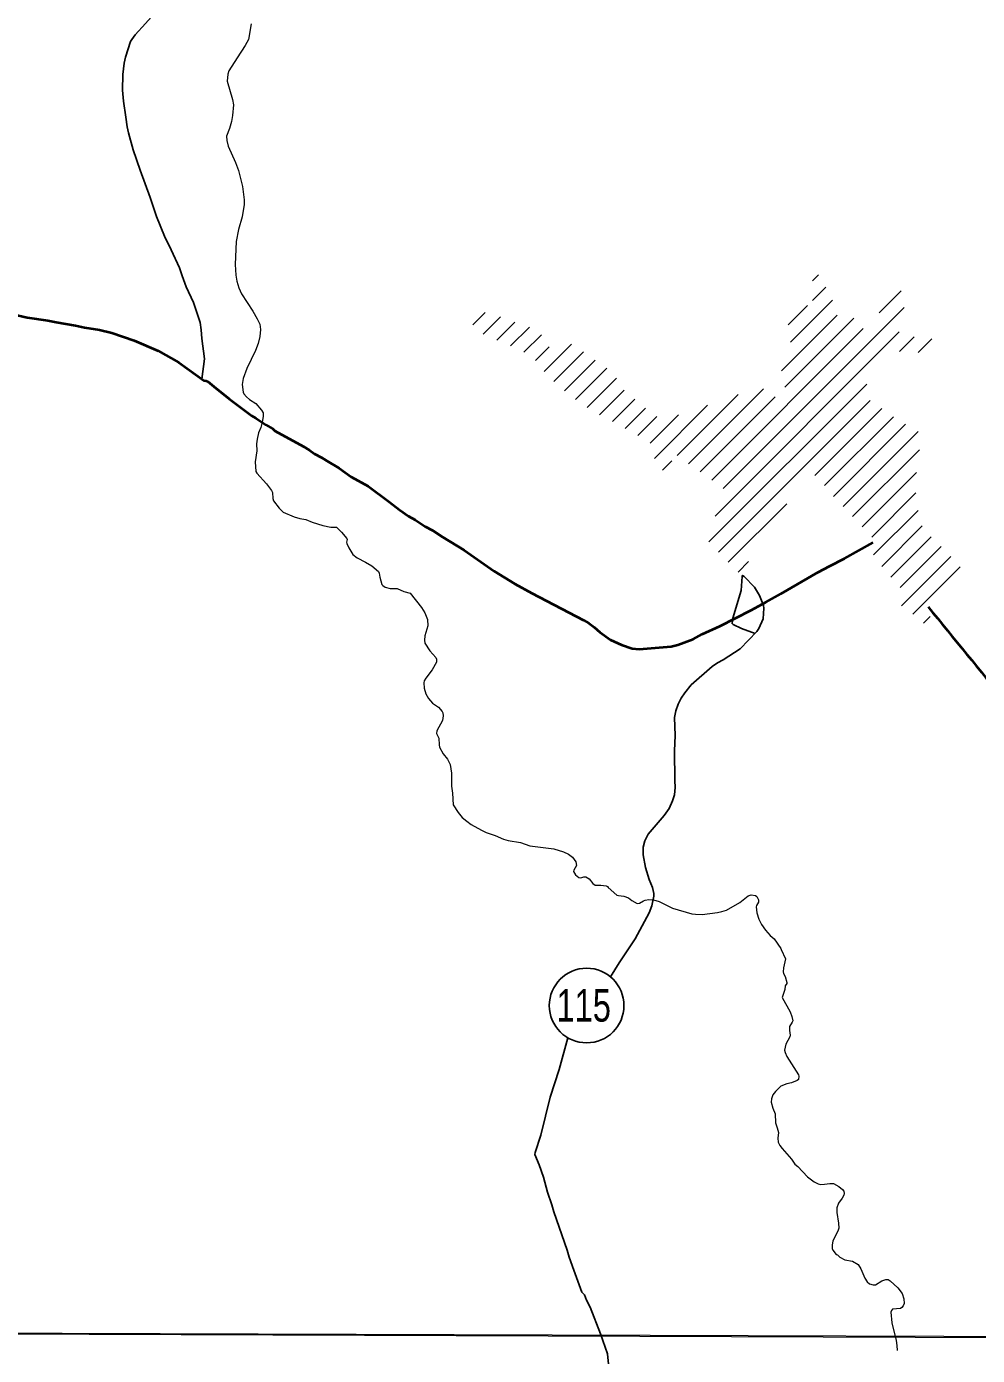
# Model space of a CAD drawing. Extents: x 553962 to 842807, y 8883888 to 9032388.
# Drawn here: x 614032 to 616078, y 8909821 to 8912681 of the extents above; entities that cross this region are included whole.
import ezdxf
from ezdxf.enums import TextEntityAlignment as Align

# ---------------------------------------------------------------- set-up
doc = ezdxf.new("R2010")
doc.units = 0
doc.header["$LTSCALE"] = 150
doc.layers.add('6', color=7, linetype='Continuous', lineweight=13)

msp = doc.modelspace()

# ---------------------------------------------------------------- linework, layer by layer
at = {"layer": '6'}
for p, q in [((615722.8, 8912133.8), (615735.8, 8912146.7)), ((615723.1, 8912091.6), (615751.6, 8912120.1)), ((615866.2, 8912064.9), (615913.5, 8912112.3)), ((615675.8, 8912001.9), (615765.9, 8912092)), ((614991.9, 8912039.2), (615018.6, 8912065.9)), ((615014.2, 8912019), (615051.5, 8912056.4)), ((615530.8, 8911687.2), (615920.2, 8912076.6)), ((615656.6, 8911940.3), (615776.4, 8912060.1)), ((615663.6, 8911904.8), (615812.3, 8912053.5)), ((615670.7, 8912039.2), (615712.3, 8912080.8)), ((615043.8, 8912006.3), (615082.5, 8912044.9)), ((615073.5, 8911993.6), (615114.1, 8912034.1)), ((615506.2, 8911705), (615832.4, 8912031.2)), ((615102.3, 8911979.9), (615140.1, 8912017.8)), ((615145.9, 8911938.7), (615204.6, 8911997.4)), ((615513.3, 8911627.3), (615909.8, 8912023.7)), ((615910.3, 8911981.8), (615942, 8912013.5)), ((615950.2, 8911979.3), (615979.5, 8912008.6)), ((615127, 8911962.2), (615156.3, 8911991.4)), ((615166.7, 8911917), (615230.7, 8911981)), ((615189.2, 8911897.1), (615255.5, 8911963.4)), ((615213, 8911878.5), (615280.3, 8911945.8)), ((615238.2, 8911861.3), (615301.4, 8911924.5)), ((615500.3, 8911571.8), (615839.7, 8911911.2)), ((615265.1, 8911845.7), (615317.8, 8911898.4)), ((615431.6, 8911757.6), (615562.9, 8911888.9)), ((615456.2, 8911739.8), (615617.5, 8911901.2)), ((615481.7, 8911722.9), (615642.7, 8911883.9)), ((615292.7, 8911830.9), (615340.7, 8911878.9)), ((615320.2, 8911816), (615363.8, 8911859.6)), ((615382.8, 8911751.2), (615497.4, 8911865.9)), ((615521.1, 8911550.2), (615847.5, 8911876.6)), ((615728.4, 8911715.1), (615872.1, 8911858.8)), ((615347.4, 8911800.8), (615388.4, 8911841.7)), ((615373.7, 8911784.6), (615434.8, 8911845.7)), ((615748.9, 8911693.2), (615897, 8911841.2)), ((615768.1, 8911669.9), (615923.5, 8911825.3)), ((615788.8, 8911648.1), (615950.1, 8911809.5)), ((615809.4, 8911626.3), (615953.2, 8911770.2)), ((615400.2, 8911726.3), (615420.1, 8911746.2)), ((615830, 8911604.6), (615946.5, 8911721.1)), ((615541.9, 8911528.6), (615667.5, 8911654.2)), ((615850.5, 8911582.5), (615945.5, 8911677.5)), ((615854.5, 8911544.2), (615950.1, 8911639.7)), ((615872.1, 8911519.3), (615959.2, 8911606.5)), ((615891.5, 8911496.3), (615978.4, 8911583.2)), ((615911.6, 8911474), (616000, 8911562.4)), ((615914.5, 8911434.4), (616020.8, 8911540.8)), ((615562.9, 8911507.2), (615585.5, 8911529.7)), ((615938.9, 8911416.4), (616040.5, 8911518)), ((615961.7, 8911396.8), (615976.5, 8911411.6)), ((574653.9, 8910009.3), (626625.7, 8909822.1))]:
    msp.add_line(p, q, dxfattribs=at)
at = {"layer": '6', "lineweight": 25}
msp.add_line((615138.8, 8910295.4), (615126.6, 8910258.3), dxfattribs=at)
for points in [[(614353.8, 8912761.2), (614336.9, 8912742.6), (614312.7, 8912712.9), (614299.8, 8912700.8), (614288.1, 8912687.2), (614265.4, 8912663), (614258.3, 8912653.2), (614256, 8912648.7), (614244.8, 8912614.9), (614242.1, 8912602.1), (614238.8, 8912578), (614238.7, 8912544.3), (614240.6, 8912520.4), (614245.5, 8912486.2)], [(614245.5, 8912486.2), (614248.5, 8912465.4), (614251.4, 8912452.5), (614261.7, 8912415.4), (614276.3, 8912371.6), (614298, 8912313.3), (614311.5, 8912271.9), (614311.5, 8912271.9), (614328.6, 8912229.8), (614343.1, 8912200.7), (614360.8, 8912161.7), (614367, 8912144.3)], [(614367, 8912144.3), (614375.3, 8912120.7), (614391.5, 8912087.1), (614405.8, 8912044.1), (614407.9, 8912028.6), (614409.2, 8912009.7), (614415.2, 8911965.8), (614409.2, 8911922.5)], [(615599.9, 8911375), (615570.6, 8911385.8), (615552.6, 8911394.1), (615550.1, 8911396.3), (615552, 8911408.1), (615569.5, 8911467.6), (615571.8, 8911497.7), (615572.6, 8911500), (615576.1, 8911497.3), (615598, 8911474.4), (615609.3, 8911456.9), (615617.4, 8911434.8), (615618, 8911429.4), (615616.8, 8911406.4), (615607.9, 8911385.5), (615603.3, 8911379.1), (615567.2, 8911342.2), (615530.8, 8911318.5), (615518.9, 8911311.9), (615507.1, 8911303.9), (615461.7, 8911264.1), (615448.1, 8911247.4), (615440.7, 8911235.9), (615434.2, 8911222.9), (615429.1, 8911208.4), (615426.1, 8911193.8), (615427.6, 8911155.1), (615426.4, 8911122.4), (615426.8, 8911058.8), (615427.6, 8911043.4), (615425.9, 8911028), (615422.1, 8911015), (615414.6, 8910998.4), (615403.9, 8910983.4), (615369.6, 8910943.1), (615362.5, 8910929), (615358.7, 8910915.2), (615358.7, 8910898.9), (615363.5, 8910871.4), (615371.8, 8910845.5), (615378.5, 8910828.5), (615382, 8910815.5), (615381.8, 8910809.8), (615377.1, 8910788.9), (615371.3, 8910773.5), (615341.2, 8910717.8), (615307.1, 8910666.5), (615288.4, 8910636.1)], [(615196.8, 8910504.9), (615177.9, 8910436.4), (615158.9, 8910377.1), (615138.8, 8910295.4)], [(615126.6, 8910258.3), (615125.9, 8910253.6), (615134.7, 8910231.8), (615144, 8910204.7), (615152.8, 8910172.4), (615162.3, 8910145.7), (615166.8, 8910130.4), (615195.1, 8910047.8), (615199.5, 8910032.8), (615209.6, 8910005.2)], [(615209.6, 8910005.2), (615227, 8909957.6), (615232.7, 8909951.5), (615237, 8909940.3), (615244.4, 8909924.9), (615267.1, 8909868.1), (615282, 8909824.9)], [(615282, 8909824.9), (615292.5, 8909716.1), (615320.5, 8909565.2), (615327.5, 8909531.6), (615344.7, 8909497.9), (615365.9, 8909445.9), (615390.2, 8909408.2), (615414.6, 8909376.6), (615454.1, 8909327.6), (615483.5, 8909293.9), (615556.6, 8909207.2), (615624.7, 8909143.6), (615643.3, 8909127.9), (615658.6, 8909118.9)]]:
    msp.add_lwpolyline(points, dxfattribs=at)
at = {"layer": '6'}
for points in [[(614515.1, 8912686.6), (614509.3, 8912653.2), (614502.2, 8912639.9), (614484.8, 8912613.7), (614467.5, 8912585.5), (614465.3, 8912578.2), (614464, 8912563.3), (614475.1, 8912524.1), (614477.1, 8912512.2), (614475.3, 8912489.2), (614472.9, 8912476.4), (614468.8, 8912461.3), (614462.4, 8912445.2), (614462.6, 8912435.7), (614465.5, 8912423.8), (614481.8, 8912388.7), (614488.3, 8912371.2), (614496.7, 8912337), (614500.2, 8912308.2), (614500.5, 8912297.9), (614495.6, 8912271.6), (614487.7, 8912244.4), (614483.1, 8912218.1), (614480.7, 8912168.7), (614482.5, 8912145.7), (614484.5, 8912132.9)], [(614515.1, 8912686.6), (614509.3, 8912653.2), (614502.2, 8912639.9), (614484.8, 8912613.7), (614467.5, 8912585.5), (614465.3, 8912578.2), (614464, 8912563.3), (614475.1, 8912524.1), (614477.1, 8912512.2), (614475.3, 8912489.2), (614472.9, 8912476.4), (614468.8, 8912461.3), (614462.4, 8912445.2), (614462.6, 8912435.7), (614465.5, 8912423.8), (614481.8, 8912388.7), (614488.3, 8912371.2), (614496.7, 8912337), (614500.2, 8912308.2), (614500.5, 8912297.9), (614495.6, 8912271.6), (614487.7, 8912244.4), (614483.1, 8912218.1), (614480.7, 8912168.7), (614482.5, 8912145.7), (614484.5, 8912132.9)], [(614484.5, 8912132.9), (614488.5, 8912118.5), (614494.8, 8912105.6), (614519, 8912068.7), (614528.5, 8912052.3), (614533.6, 8912040.3), (614535.2, 8912029.2), (614534.1, 8912013.9), (614530.5, 8911998.8), (614524.3, 8911983.7), (614505.6, 8911945.2), (614498.3, 8911923.7), (614495.8, 8911911), (614498.1, 8911894.5), (614499.6, 8911890.4), (614505.2, 8911884.2), (614511.7, 8911878.7), (614525.4, 8911869.5), (614537.6, 8911855.5), (614541.2, 8911849.9), (614540.9, 8911842.1), (614539, 8911829.5), (614535.8, 8911818.4), (614530.9, 8911806.4), (614528.1, 8911793), (614527.1, 8911782.7), (614527.6, 8911768.3), (614524, 8911744.5), (614525, 8911723.2), (614527.2, 8911719.7), (614548.6, 8911697.1), (614559.2, 8911682.3), (614561, 8911678.1), (614562.1, 8911665.3), (614563.3, 8911660.1), (614575.8, 8911644.3), (614584.1, 8911636.2)], [(614484.5, 8912132.9), (614488.5, 8912118.5), (614494.8, 8912105.6), (614519, 8912068.7), (614528.5, 8912052.3), (614533.6, 8912040.3), (614535.2, 8912029.2), (614534.1, 8912013.9), (614530.5, 8911998.8), (614524.3, 8911983.7), (614505.6, 8911945.2), (614498.3, 8911923.7), (614495.8, 8911911), (614498.1, 8911894.5), (614499.6, 8911890.4), (614505.2, 8911884.2), (614511.7, 8911878.7), (614525.4, 8911869.5), (614537.6, 8911855.5), (614541.2, 8911849.9), (614540.9, 8911842.1), (614539, 8911829.5), (614535.8, 8911818.4), (614530.9, 8911806.4), (614528.1, 8911793), (614527.1, 8911782.7), (614527.6, 8911768.3), (614524, 8911744.5), (614525, 8911723.2), (614527.2, 8911719.7), (614548.6, 8911697.1), (614559.2, 8911682.3), (614561, 8911678.1), (614562.1, 8911665.3), (614563.3, 8911660.1), (614575.8, 8911644.3), (614584.1, 8911636.2)], [(614584.1, 8911636.2), (614584.1, 8911636.2), (614608.1, 8911626), (614620.1, 8911622.5), (614632.8, 8911620.1), (614646.4, 8911614.5), (614669.5, 8911607.6), (614686.7, 8911603.6), (614699.1, 8911603.5)], [(614584.1, 8911636.2), (614584.1, 8911636.2), (614608.1, 8911626), (614620.1, 8911622.5), (614632.8, 8911620.1), (614646.4, 8911614.5), (614669.5, 8911607.6), (614686.7, 8911603.6), (614699.1, 8911603.5)], [(614699.1, 8911603.5), (614709.6, 8911592.7), (614721, 8911579.5), (614721.7, 8911577.4), (614720.5, 8911571.3), (614720.9, 8911568.5), (614725.2, 8911559.5), (614733.7, 8911545.2), (614743, 8911537.5), (614761.4, 8911528.7), (614774.6, 8911520.4), (614789, 8911508.1), (614790.7, 8911504.8), (614791.9, 8911496.1), (614796.7, 8911480.4), (614798.5, 8911478), (614803.8, 8911474.7), (614814.1, 8911471.6), (614829.7, 8911471.7), (614843.8, 8911465.2), (614857.7, 8911461.5)], [(614699.1, 8911603.5), (614709.6, 8911592.7), (614721, 8911579.5), (614721.7, 8911577.4), (614720.5, 8911571.3), (614720.9, 8911568.5), (614725.2, 8911559.5), (614733.7, 8911545.2), (614743, 8911537.5), (614761.4, 8911528.7), (614774.6, 8911520.4), (614789, 8911508.1), (614790.7, 8911504.8), (614791.9, 8911496.1), (614796.7, 8911480.4), (614798.5, 8911478), (614803.8, 8911474.7), (614814.1, 8911471.6), (614829.7, 8911471.7), (614843.8, 8911465.2), (614857.7, 8911461.5)], [(614857.7, 8911461.5), (614881.8, 8911430.8), (614888.6, 8911419.2), (614894.8, 8911405.2)], [(614857.7, 8911461.5), (614881.8, 8911430.8), (614888.6, 8911419.2), (614894.8, 8911405.2)], [(614894.8, 8911405.2), (614895.4, 8911391.4), (614888.9, 8911370.2), (614888.4, 8911360.8), (614889.1, 8911353.8), (614899.5, 8911337.6), (614912.4, 8911323), (614913.7, 8911319.3), (614914.2, 8911313.3), (614904.9, 8911296.6), (614891.1, 8911278.7), (614887.5, 8911272.7), (614886.7, 8911268.4), (614887.5, 8911257.1), (614891.3, 8911245.4), (614896.7, 8911234.7), (614905.3, 8911224.8), (614918.6, 8911216.5), (614926.2, 8911207.2), (614927.8, 8911204), (614928.2, 8911197.9), (614926.8, 8911187.5), (614914.6, 8911165.4), (614913.8, 8911159.4), (614919.2, 8911149.3), (614919.5, 8911135.1), (614920.4, 8911130.5), (614928.7, 8911116), (614938, 8911104.3), (614943.4, 8911093.3), (614946.1, 8911074.3), (614946.5, 8911046), (614948.7, 8911031.5), (614949.6, 8911006.3), (614960.5, 8910989.7), (614969.6, 8910979.2), (614979.4, 8910970.7), (614988.7, 8910963.9), (615010.6, 8910951.4), (615020.6, 8910946.9), (615040, 8910940.5), (615058, 8910932.4), (615068.1, 8910929.7), (615094.7, 8910924.8), (615114.8, 8910917.8), (615166.8, 8910911.8), (615187.2, 8910905), (615197.9, 8910900.2), (615206.5, 8910893.3), (615213.6, 8910883.4), (615215, 8910876), (615209.8, 8910865.4), (615209.1, 8910862.7), (615213.4, 8910855.6), (615220.2, 8910850.1), (615223.2, 8910849.3), (615226.8, 8910849.7), (615230.9, 8910851.5), (615235.7, 8910851.1), (615242.4, 8910846.7), (615250.7, 8910837.1), (615255.1, 8910833.3), (615267.9, 8910833.6), (615278.9, 8910832), (615282.1, 8910830.2)], [(614894.8, 8911405.2), (614895.4, 8911391.4), (614888.9, 8911370.2), (614888.4, 8911360.8), (614889.1, 8911353.8), (614899.5, 8911337.6), (614912.4, 8911323), (614913.7, 8911319.3), (614914.2, 8911313.3), (614904.9, 8911296.6), (614891.1, 8911278.7), (614887.5, 8911272.7), (614886.7, 8911268.4), (614887.5, 8911257.1), (614891.3, 8911245.4), (614896.7, 8911234.7), (614905.3, 8911224.8), (614918.6, 8911216.5), (614926.2, 8911207.2), (614927.8, 8911204), (614928.2, 8911197.9), (614926.8, 8911187.5), (614914.6, 8911165.4), (614913.8, 8911159.4), (614919.2, 8911149.3), (614919.5, 8911135.1), (614920.4, 8911130.5), (614928.7, 8911116), (614938, 8911104.3), (614943.4, 8911093.3), (614946.1, 8911074.3), (614946.5, 8911046), (614948.7, 8911031.5), (614949.6, 8911006.3), (614960.5, 8910989.7), (614969.6, 8910979.2), (614979.4, 8910970.7), (614988.7, 8910963.9), (615010.6, 8910951.4), (615020.6, 8910946.9), (615040, 8910940.5), (615058, 8910932.4), (615068.1, 8910929.7), (615094.7, 8910924.8), (615114.8, 8910917.8), (615166.8, 8910911.8), (615187.2, 8910905), (615197.9, 8910900.2), (615206.5, 8910893.3), (615213.6, 8910883.4), (615215, 8910876), (615209.8, 8910865.4), (615209.1, 8910862.7), (615213.4, 8910855.6), (615220.2, 8910850.1), (615223.2, 8910849.3), (615226.8, 8910849.7), (615230.9, 8910851.5), (615235.7, 8910851.1), (615242.4, 8910846.7), (615250.7, 8910837.1), (615255.1, 8910833.3), (615267.9, 8910833.6), (615278.9, 8910832), (615282.1, 8910830.2)], [(615282.1, 8910830.2), (615283.3, 8910828.4), (615301.8, 8910812), (615305.6, 8910810.9), (615317.4, 8910809.9), (615327, 8910806.2), (615334.1, 8910800.2), (615345.7, 8910794.2), (615350.8, 8910794.5), (615359.4, 8910799.7), (615362.8, 8910800.9), (615370.9, 8910802.2), (615381.1, 8910801.7), (615392.8, 8910798.4), (615422.1, 8910783.9), (615463.6, 8910771.7), (615471.6, 8910770.6), (615485.6, 8910770.5), (615518.7, 8910774.5), (615528.2, 8910776.4), (615537.8, 8910779.3), (615566.4, 8910796.3), (615584.6, 8910810.5), (615590.8, 8910812.2), (615600.7, 8910811.2), (615603.2, 8910808.9), (615606.8, 8910802), (615606.7, 8910796.5), (615602.9, 8910789.8), (615602.2, 8910786.7), (615603.2, 8910774.1), (615607.3, 8910759.9), (615613.3, 8910748.7), (615621.7, 8910736.7), (615632.2, 8910724.8), (615640.6, 8910717.5), (615655, 8910696.9)], [(615282.1, 8910830.2), (615283.3, 8910828.4), (615301.8, 8910812), (615305.6, 8910810.9), (615317.4, 8910809.9), (615327, 8910806.2), (615334.1, 8910800.2), (615345.7, 8910794.2), (615350.8, 8910794.5), (615359.4, 8910799.7), (615362.8, 8910800.9), (615370.9, 8910802.2), (615381.1, 8910801.7), (615392.8, 8910798.4), (615422.1, 8910783.9), (615463.6, 8910771.7), (615471.6, 8910770.6), (615485.6, 8910770.5), (615518.7, 8910774.5), (615528.2, 8910776.4), (615537.8, 8910779.3), (615566.4, 8910796.3), (615584.6, 8910810.5), (615590.8, 8910812.2), (615600.7, 8910811.2), (615603.2, 8910808.9), (615606.8, 8910802), (615606.7, 8910796.5), (615602.9, 8910789.8), (615602.2, 8910786.7), (615603.2, 8910774.1), (615607.3, 8910759.9), (615613.3, 8910748.7), (615621.7, 8910736.7), (615632.2, 8910724.8), (615640.6, 8910717.5), (615655, 8910696.9)], [(615655, 8910696.9), (615656, 8910695), (615665, 8910674.5), (615660.6, 8910655.1), (615659.8, 8910646.5), (615660.9, 8910642.9), (615664.4, 8910636.8), (615668, 8910623.7), (615667.6, 8910622), (615664, 8910616.7), (615663.2, 8910608.5), (615658, 8910591.3), (615674.8, 8910560.7), (615678.6, 8910550.5), (615680.5, 8910541.2), (615679.6, 8910538.6), (615673.4, 8910528.9), (615673.3, 8910520.8), (615674.8, 8910510.7), (615674.5, 8910507.1), (615665.9, 8910491.1), (615662.8, 8910478.6), (615664, 8910473.1), (615667.5, 8910464.5), (615692.6, 8910424.9), (615693.7, 8910422.2), (615692.8, 8910415.3), (615690.4, 8910413.3), (615677.6, 8910408), (615667.7, 8910405.9), (615654.9, 8910400.8), (615643.2, 8910389.5), (615638, 8910382.3), (615634.6, 8910373.3), (615634, 8910366.5), (615637.8, 8910353.2), (615642.9, 8910341.4), (615643.7, 8910321.8), (615647.4, 8910310.9), (615649.7, 8910301.3), (615648.6, 8910289.1), (615649.3, 8910280.6), (615652.9, 8910273.4), (615657.9, 8910266.5), (615678, 8910244), (615684.8, 8910233.2), (615691.8, 8910227.6), (615712.5, 8910205.7), (615726.4, 8910195.1), (615735.1, 8910190.5), (615740.5, 8910189), (615748.6, 8910189.6), (615760.2, 8910191.7), (615768.2, 8910191.4), (615779.6, 8910185.2), (615787.6, 8910178.1), (615790.3, 8910174.6), (615791.2, 8910169.9), (615790.2, 8910166.1), (615787, 8910159.5), (615778.9, 8910148.9), (615775.1, 8910139), (615775.4, 8910128.9), (615779, 8910106.3), (615779.6, 8910095.5)], [(615655, 8910696.9), (615656, 8910695), (615665, 8910674.5), (615660.6, 8910655.1), (615659.8, 8910646.5), (615660.9, 8910642.9), (615664.4, 8910636.8), (615668, 8910623.7), (615667.6, 8910622), (615664, 8910616.7), (615663.2, 8910608.5), (615658, 8910591.3), (615674.8, 8910560.7), (615678.6, 8910550.5), (615680.5, 8910541.2), (615679.6, 8910538.6), (615673.4, 8910528.9), (615673.3, 8910520.8), (615674.8, 8910510.7), (615674.5, 8910507.1), (615665.9, 8910491.1), (615662.8, 8910478.6), (615664, 8910473.1), (615667.5, 8910464.5), (615692.6, 8910424.9), (615693.7, 8910422.2), (615692.8, 8910415.3), (615690.4, 8910413.3), (615677.6, 8910408), (615667.7, 8910405.9), (615654.9, 8910400.8), (615643.2, 8910389.5), (615638, 8910382.3), (615634.6, 8910373.3), (615634, 8910366.5), (615637.8, 8910353.2), (615642.9, 8910341.4), (615643.7, 8910321.8), (615647.4, 8910310.9), (615649.7, 8910301.3), (615648.6, 8910289.1), (615649.3, 8910280.6), (615652.9, 8910273.4), (615657.9, 8910266.5), (615678, 8910244), (615684.8, 8910233.2), (615691.8, 8910227.6), (615712.5, 8910205.7), (615726.4, 8910195.1), (615735.1, 8910190.5), (615740.5, 8910189), (615748.6, 8910189.6), (615760.2, 8910191.7), (615768.2, 8910191.4), (615779.6, 8910185.2), (615787.6, 8910178.1), (615790.3, 8910174.6), (615791.2, 8910169.9), (615790.2, 8910166.1), (615787, 8910159.5), (615778.9, 8910148.9), (615775.1, 8910139), (615775.4, 8910128.9), (615779, 8910106.3), (615779.6, 8910095.5)], [(615779.6, 8910095.5), (615777.8, 8910089), (615767.1, 8910068), (615765.5, 8910058.6), (615765.6, 8910051.5), (615766.8, 8910047.7), (615773.9, 8910038.9), (615776.6, 8910037.6), (615782, 8910032.8), (615792.4, 8910027.4), (615808.9, 8910024.1), (615821.1, 8910017.4), (615827.3, 8910008), (615836, 8909987.3), (615840.8, 8909979.7), (615845.5, 8909975.1), (615853.4, 8909973.2), (615858.7, 8909973.1)], [(615779.6, 8910095.5), (615777.8, 8910089), (615767.1, 8910068), (615765.5, 8910058.6), (615765.6, 8910051.5), (615766.8, 8910047.7), (615773.9, 8910038.9), (615776.6, 8910037.6), (615782, 8910032.8), (615792.4, 8910027.4), (615808.9, 8910024.1), (615821.1, 8910017.4), (615827.3, 8910008), (615836, 8909987.3), (615840.8, 8909979.7), (615845.5, 8909975.1), (615853.4, 8909973.2), (615858.7, 8909973.1)], [(615858.7, 8909973.1), (615872.3, 8909982.2), (615872.3, 8909982.2), (615880.5, 8909984.9), (615885.6, 8909985), (615890.5, 8909981.6), (615906.4, 8909966.9), (615915.9, 8909954.7), (615919.4, 8909943.5), (615920.1, 8909933.2), (615918.5, 8909928), (615915.6, 8909924.2), (615912.6, 8909922.4), (615895.5, 8909920.7), (615893.3, 8909918.3), (615891.8, 8909914.3), (615893.8, 8909891.8), (615903, 8909853.2), (615904.8, 8909843), (615905.3, 8909832)], [(615858.7, 8909973.1), (615872.3, 8909982.2), (615872.3, 8909982.2), (615880.5, 8909984.9), (615885.6, 8909985), (615890.5, 8909981.6), (615906.4, 8909966.9), (615915.9, 8909954.7), (615919.4, 8909943.5), (615920.1, 8909933.2), (615918.5, 8909928), (615915.6, 8909924.2), (615912.6, 8909922.4), (615895.5, 8909920.7), (615893.3, 8909918.3), (615891.8, 8909914.3), (615893.8, 8909891.8), (615903, 8909853.2), (615904.8, 8909843), (615905.3, 8909832)]]:
    msp.add_lwpolyline(points, dxfattribs=at)
at = {"layer": '6', "lineweight": 40}
for points in [[(614002.3, 8912061.8), (614033.2, 8912054.9), (614077.8, 8912048.2), (614095.5, 8912045.1)], [(614095.5, 8912045.1), (614137.1, 8912037.7), (614156.6, 8912033.3), (614189.2, 8912028.5), (614215.5, 8912021.7), (614263.5, 8912005.4), (614314.9, 8911983.3), (614359.3, 8911958.1), (614413.5, 8911919.6), (614418.7, 8911918.6), (614421.7, 8911917.2), (614435.2, 8911906.1)], [(614435.2, 8911906.1), (614467.8, 8911879.5), (614516.5, 8911843.4), (614525, 8911838.5), (614546.8, 8911823.9), (614561.7, 8911815.5), (614566.3, 8911811.2), (614628, 8911777.5), (614641.1, 8911769.4), (614651.5, 8911761.7), (614666.3, 8911753.9), (614677.9, 8911746.1), (614704.5, 8911730.6), (614730.4, 8911712.3), (614767.2, 8911691.7), (614812.1, 8911658)], [(614812.1, 8911658), (614834.3, 8911641.2), (614853.5, 8911627.7), (614868.4, 8911619.3), (614889.4, 8911605.2), (614904.7, 8911597), (614927.5, 8911582), (614973.7, 8911554), (615037.8, 8911508.7), (615082.7, 8911481.4), (615119.3, 8911462), (615230, 8911403.5)], [(615622.9, 8911442.5), (615654.7, 8911459.9), (615735.5, 8911507.1), (615759.3, 8911519.9), (615791.8, 8911536), (615853.7, 8911570.5)], [(615230, 8911403.5), (615241.5, 8911397.4), (615253.3, 8911388.6), (615265.3, 8911377.7), (615288.5, 8911361.6), (615312.4, 8911350.8), (615334.8, 8911342.9), (615350.2, 8911341), (615419.2, 8911347.2), (615433.5, 8911350.8), (615466.3, 8911362.9), (615486, 8911373.3), (615523.5, 8911390.4), (615590.8, 8911424.9), (615622.9, 8911442.5)]]:
    msp.add_lwpolyline(points, dxfattribs=at)
at = {"layer": '6'}
msp.add_lwpolyline([(618535.2, 8909853.3), (607574.3, 8909890.7), (607543.3, 8898835.3), (618504.2, 8898795.8)], close=True, dxfattribs=at)
at = {"layer": '6', "lineweight": 25}
msp.add_circle((615237.1, 8910574.3), 80.3, dxfattribs=at)
at = {"layer": '6', "lineweight": 40}
msp.add_spline([(615971.7, 8911432.5), (616138.5, 8911227.2), (616313.3, 8911009), (616504.8, 8910771.9), (616895.5, 8910293.3), (617079.2, 8910062.8), (617725.5, 8909265.3), (618056.1, 8908857.7), (618263.2, 8908603.7), (618306.6, 8908556.9), (618336.6, 8908483.4), (618463.5, 8908212.8), (618533.7, 8908055.7), (618557.1, 8908012.3), (618590.5, 8907985.6), (618640.6, 8907962.2), (618764.1, 8907925.4), (618847.6, 8907882), (618877.7, 8907865.3), (618937.8, 8907811.8), (618997.9, 8907778.4), (619028, 8907745), (619141.5, 8907698.2), (619241.7, 8907674.8), (619372, 8907724.9), (619488.8, 8907801.8), (619552.3, 8907878.6), (619575.7, 8907905.4), (619599.1, 8907898.7), (619632.5, 8907871.9), (619679.2, 8907871.9), (619782.8, 8907918.7), (619872.9, 8907952.1), (619949.7, 8907952.1), (620026.6, 8907932.1), (620080, 8907908.7), (620120.1, 8907902), (620166.8, 8907932.1), (620233.6, 8907952.1), (620300.4, 8907958.8), (620363.9, 8907992.2), (620444, 8908052.4), (620517.5, 8908095.8), (620586.9, 8908115.3)], degree=3, dxfattribs=at)

# ---------------------------------------------------------------- texts
at = {"layer": '6', "width": 0.75}
msp.add_text('115', height=70, dxfattribs=at).set_placement((615230.8, 8910539.7), align=Align.CENTER)

doc.saveas('drawing.dxf')
